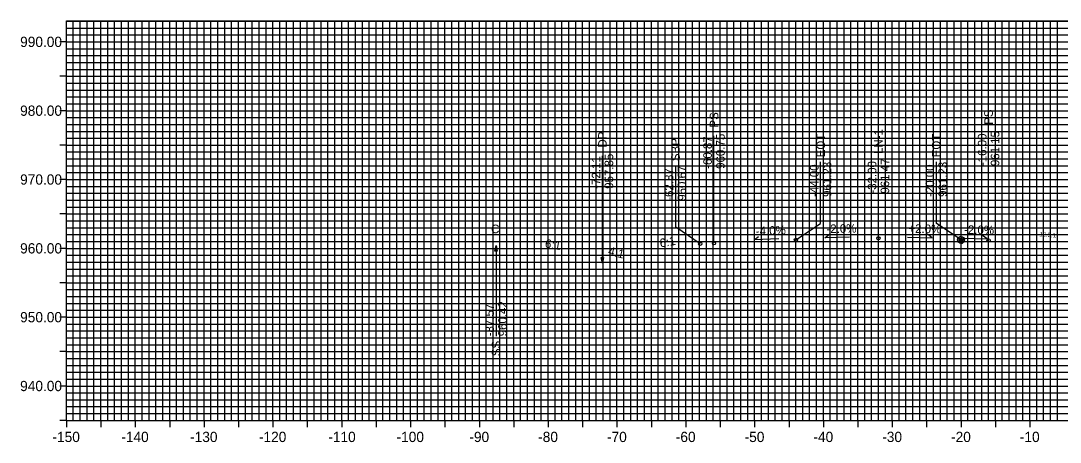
# Model space of a CAD drawing. Extents: x -157 to 156, y 932 to 993.
# Drawn here: x -156.6 to -5.6, y 931.8 to 993.1 of the extents above; entities that cross this region are included whole.
import ezdxf

# ---------------------------------------------------------------- set-up
doc = ezdxf.new("R2010")
doc.units = 0
for name, color, linetype in [('E_NCDOT_Terrain_Model_Boundary', 7, 'Continuous'), ('E_NCDOT_Terrain_Model_Breakline', 7, 'Continuous'), ('E_NCDOT_Terrain_Model_Contour_Minor', 7, 'Continuous'), ('E_NCDOT_Terrain_Model_Flow_Arrows', 7, 'Continuous'), ('E_NCDOT_Terrain_Model_Hole', 7, 'Continuous'), ('E_NCDOT_Terrain_Model_Island', 7, 'Continuous'), ('E_NCDOT_Terrain_Model_Points_High', 7, 'Continuous'), ('E_NCDOT_Terrain_Model_Points_Low', 7, 'Continuous'), ('E_NCDOT_Terrain_Model_Triangles', 7, 'Continuous'), ('E_NCDOT_Vertical_Profile_Ground_Line', 7, 'Continuous'), ('P_HYD_Contour_Major', 7, 'Continuous'), ('P_HYD_Contour_Minor', 7, 'Continuous'), ('P_HYD_TL_Ditch_Boundary', 7, 'Continuous')]:
    doc.layers.add(name, color=color, linetype=linetype)

msp = doc.modelspace()

# ---------------------------------------------------------------- linework, layer by layer
at = {"layer": 'E_NCDOT_Terrain_Model_Boundary'}
for p, q in [((-50.07, 961.23), (-49.41, 961.73)), ((-46.48, 961.37), (-50.07, 961.23)), ((-39.8, 961.55), (-39.12, 962.05)), ((-36.2, 961.62), (-39.8, 961.55)), ((-27.8, 961.62), (-24.2, 961.55)), ((-24.2, 961.55), (-24.88, 962.05)), ((-19.8, 961.46), (-16.2, 961.39)), ((-16.2, 961.39), (-16.88, 961.89))]:
    msp.add_line(p, q, dxfattribs=at)
at = {"layer": 'E_NCDOT_Terrain_Model_Breakline'}
for p, q in [((-140, 935), (-140, 993.06)), ((-130, 935), (-130, 993.06)), ((-120, 935), (-120, 993.06)), ((-110, 935), (-110, 993.06)), ((-100, 935), (-100, 993.06)), ((-90, 935), (-90, 993.06)), ((-80, 935), (-80, 993.06)), ((-70, 935), (-70, 993.06)), ((-60, 935), (-60, 993.06)), ((-50, 935), (-50, 993.06)), ((-40, 935), (-40, 993.06)), ((-30, 935), (-30, 993.06)), ((-20, 935), (-20, 993.06)), ((-10, 935), (-10, 993.06)), ((-150, 990), (150, 990)), ((-150, 980), (150, 980)), ((-150, 970), (150, 970)), ((-150, 960), (150, 960)), ((-150, 950), (150, 950)), ((-150, 940), (150, 940))]:
    msp.add_line(p, q, dxfattribs=at)
at = {"layer": 'E_NCDOT_Terrain_Model_Flow_Arrows'}
for p, q in [((-150, 993.06), (150, 993.06)), ((-150, 935), (-150, 993.06)), ((-150, 935), (150, 935))]:
    msp.add_line(p, q, dxfattribs=at)
at = {"layer": 'E_NCDOT_Terrain_Model_Island'}
for p, q in [((-20.5, 961.23), (-19.5, 961.23)), ((-20.5, 961.23), (-19.5, 961.23)), ((-20, 961.73), (-20, 960.73)), ((-20, 961.73), (-20, 960.73))]:
    msp.add_line(p, q, dxfattribs=at)
for points in [[(-20.5, 961.23), (-20, 961.23), (-20, 961.73)], [(-20.5, 961.23), (-20, 961.23), (-20, 961.73)], [(-19.5, 961.23), (-20, 961.23), (-20, 960.73)], [(-19.5, 961.23), (-20, 961.23), (-20, 960.73)]]:
    msp.add_lwpolyline(points, dxfattribs=at)
msp.add_circle((-20, 961.23), 0.5, dxfattribs=at)
msp.add_circle((-20, 961.23), 0.5, dxfattribs=at)
for start, end in [(90, 180), (90, 180), (270, 0), (270, 0)]:
    msp.add_arc((-20, 961.23), 0.5, start, end, dxfattribs=at)
at = {"layer": 'E_NCDOT_Terrain_Model_Points_High'}
for p, q in [((-150, 993), (150, 993)), ((-149, 935), (-149, 993.06)), ((-148, 935), (-148, 993.06)), ((-147, 935), (-147, 993.06)), ((-146, 935), (-146, 993.06)), ((-144, 935), (-144, 993.06)), ((-143, 935), (-143, 993.06)), ((-142, 935), (-142, 993.06)), ((-141, 935), (-141, 993.06)), ((-139, 935), (-139, 993.06)), ((-138, 935), (-138, 993.06)), ((-137, 935), (-137, 993.06)), ((-136, 935), (-136, 993.06)), ((-134, 935), (-134, 993.06)), ((-133, 935), (-133, 993.06)), ((-132, 935), (-132, 993.06)), ((-131, 935), (-131, 993.06)), ((-129, 935), (-129, 993.06)), ((-128, 935), (-128, 993.06)), ((-127, 935), (-127, 993.06)), ((-126, 935), (-126, 993.06)), ((-124, 935), (-124, 993.06)), ((-123, 935), (-123, 993.06)), ((-122, 935), (-122, 993.06)), ((-121, 935), (-121, 993.06)), ((-119, 935), (-119, 993.06)), ((-118, 935), (-118, 993.06)), ((-117, 935), (-117, 993.06)), ((-116, 935), (-116, 993.06)), ((-114, 935), (-114, 993.06)), ((-113, 935), (-113, 993.06)), ((-112, 935), (-112, 993.06)), ((-111, 935), (-111, 993.06)), ((-109, 935), (-109, 993.06)), ((-108, 935), (-108, 993.06)), ((-107, 935), (-107, 993.06)), ((-106, 935), (-106, 993.06)), ((-104, 935), (-104, 993.06)), ((-103, 935), (-103, 993.06)), ((-102, 935), (-102, 993.06)), ((-101, 935), (-101, 993.06)), ((-99, 935), (-99, 993.06)), ((-98, 935), (-98, 993.06)), ((-97, 935), (-97, 993.06)), ((-96, 935), (-96, 993.06)), ((-94, 935), (-94, 993.06)), ((-93, 935), (-93, 993.06)), ((-92, 935), (-92, 993.06)), ((-91, 935), (-91, 993.06)), ((-89, 935), (-89, 993.06)), ((-88, 935), (-88, 993.06)), ((-87, 935), (-87, 993.06)), ((-86, 935), (-86, 993.06)), ((-84, 935), (-84, 993.06)), ((-83, 935), (-83, 993.06)), ((-82, 935), (-82, 993.06)), ((-81, 935), (-81, 993.06)), ((-79, 935), (-79, 993.06)), ((-78, 935), (-78, 993.06)), ((-77, 935), (-77, 993.06)), ((-76, 935), (-76, 993.06)), ((-74, 935), (-74, 993.06)), ((-73, 935), (-73, 993.06)), ((-72, 935), (-72, 993.06)), ((-71, 935), (-71, 993.06)), ((-69, 935), (-69, 993.06)), ((-68, 935), (-68, 993.06)), ((-67, 935), (-67, 993.06)), ((-66, 935), (-66, 993.06)), ((-64, 935), (-64, 993.06)), ((-63, 935), (-63, 993.06)), ((-62, 935), (-62, 993.06)), ((-61, 935), (-61, 993.06)), ((-59, 935), (-59, 993.06)), ((-58, 935), (-58, 993.06)), ((-57, 935), (-57, 993.06)), ((-56, 935), (-56, 993.06)), ((-54, 935), (-54, 993.06)), ((-53, 935), (-53, 993.06)), ((-52, 935), (-52, 993.06)), ((-51, 935), (-51, 993.06)), ((-49, 935), (-49, 993.06)), ((-48, 935), (-48, 993.06)), ((-47, 935), (-47, 993.06)), ((-46, 935), (-46, 993.06)), ((-44, 935), (-44, 993.06)), ((-43, 935), (-43, 993.06)), ((-42, 935), (-42, 993.06)), ((-41, 935), (-41, 993.06)), ((-39, 935), (-39, 993.06)), ((-38, 935), (-38, 993.06)), ((-37, 935), (-37, 993.06)), ((-36, 935), (-36, 993.06)), ((-34, 935), (-34, 993.06)), ((-33, 935), (-33, 993.06)), ((-32, 935), (-32, 993.06)), ((-31, 935), (-31, 993.06)), ((-29, 935), (-29, 993.06)), ((-28, 935), (-28, 993.06)), ((-27, 935), (-27, 993.06)), ((-26, 935), (-26, 993.06)), ((-24, 935), (-24, 993.06)), ((-23, 935), (-23, 993.06)), ((-22, 935), (-22, 993.06)), ((-21, 935), (-21, 993.06)), ((-19, 935), (-19, 993.06)), ((-18, 935), (-18, 993.06)), ((-17, 935), (-17, 993.06)), ((-16, 935), (-16, 993.06)), ((-14, 935), (-14, 993.06)), ((-13, 935), (-13, 993.06)), ((-12, 935), (-12, 993.06)), ((-11, 935), (-11, 993.06)), ((-9, 935), (-9, 993.06)), ((-8, 935), (-8, 993.06)), ((-7, 935), (-7, 993.06)), ((-6, 935), (-6, 993.06)), ((-150, 992), (150, 992)), ((-150, 991), (150, 991)), ((-150, 989), (150, 989)), ((-150, 988), (150, 988)), ((-150, 987), (150, 987)), ((-150, 986), (150, 986)), ((-150, 984), (150, 984)), ((-150, 983), (150, 983)), ((-150, 982), (150, 982)), ((-150, 981), (150, 981)), ((-150, 979), (150, 979)), ((-150, 978), (150, 978)), ((-150, 977), (150, 977)), ((-150, 976), (150, 976)), ((-150, 974), (150, 974)), ((-150, 973), (150, 973)), ((-150, 972), (150, 972)), ((-150, 971), (150, 971)), ((-150, 969), (150, 969)), ((-150, 968), (150, 968)), ((-150, 967), (150, 967)), ((-150, 966), (150, 966)), ((-150, 964), (150, 964)), ((-150, 963), (150, 963)), ((-150, 962), (150, 962)), ((-150, 961), (150, 961)), ((-150, 959), (150, 959)), ((-150, 958), (150, 958)), ((-150, 957), (150, 957)), ((-150, 956), (150, 956)), ((-150, 954), (150, 954)), ((-150, 953), (150, 953)), ((-150, 952), (150, 952)), ((-150, 951), (150, 951)), ((-150, 949), (150, 949)), ((-150, 948), (150, 948)), ((-150, 947), (150, 947)), ((-150, 946), (150, 946)), ((-150, 944), (150, 944)), ((-150, 943), (150, 943)), ((-150, 942), (150, 942)), ((-150, 941), (150, 941)), ((-150, 939), (150, 939)), ((-150, 938), (150, 938)), ((-150, 937), (150, 937)), ((-150, 936), (150, 936))]:
    msp.add_line(p, q, dxfattribs=at)
at = {"layer": 'E_NCDOT_Terrain_Model_Points_Low'}
for p, q in [((-145, 935), (-145, 993.06)), ((-140, 935), (-140, 993.06)), ((-135, 935), (-135, 993.06)), ((-130, 935), (-130, 993.06)), ((-125, 935), (-125, 993.06)), ((-120, 935), (-120, 993.06)), ((-115, 935), (-115, 993.06)), ((-110, 935), (-110, 993.06)), ((-105, 935), (-105, 993.06)), ((-100, 935), (-100, 993.06)), ((-95, 935), (-95, 993.06)), ((-90, 935), (-90, 993.06)), ((-85, 935), (-85, 993.06)), ((-80, 935), (-80, 993.06)), ((-75, 935), (-75, 993.06)), ((-70, 935), (-70, 993.06)), ((-65, 935), (-65, 993.06)), ((-60, 935), (-60, 993.06)), ((-55, 935), (-55, 993.06)), ((-50, 935), (-50, 993.06)), ((-45, 935), (-45, 993.06)), ((-40, 935), (-40, 993.06)), ((-35, 935), (-35, 993.06)), ((-30, 935), (-30, 993.06)), ((-25, 935), (-25, 993.06)), ((-20, 935), (-20, 993.06)), ((-15, 935), (-15, 993.06)), ((-10, 935), (-10, 993.06)), ((-150, 990), (-150.96, 990)), ((-150, 990), (150, 990)), ((-150, 985), (-150.96, 985)), ((-150, 985), (150, 985)), ((-150, 980), (-150.96, 980)), ((-150, 980), (150, 980)), ((-150, 975), (-150.96, 975)), ((-150, 975), (150, 975)), ((-150, 970), (-150.96, 970)), ((-150, 970), (150, 970)), ((-150, 965), (-150.96, 965)), ((-150, 965), (150, 965)), ((-150, 960), (-150.96, 960)), ((-150, 960), (150, 960)), ((-150, 955), (-150.96, 955)), ((-150, 955), (150, 955)), ((-150, 950), (-150.96, 950)), ((-150, 950), (150, 950)), ((-150, 945), (-150.96, 945)), ((-150, 945), (150, 945)), ((-150, 940), (-150.96, 940)), ((-150, 940), (150, 940)), ((-150, 935), (-150.96, 935)), ((-150, 935), (-150, 934.04)), ((-145, 935), (-145, 934.04)), ((-140, 935), (-140, 934.04)), ((-135, 935), (-135, 934.04)), ((-130, 935), (-130, 934.04)), ((-125, 935), (-125, 934.04)), ((-120, 935), (-120, 934.04)), ((-115, 935), (-115, 934.04)), ((-110, 935), (-110, 934.04)), ((-105, 935), (-105, 934.04)), ((-100, 935), (-100, 934.04)), ((-95, 935), (-95, 934.04)), ((-90, 935), (-90, 934.04)), ((-85, 935), (-85, 934.04)), ((-80, 935), (-80, 934.04)), ((-75, 935), (-75, 934.04)), ((-70, 935), (-70, 934.04)), ((-65, 935), (-65, 934.04)), ((-60, 935), (-60, 934.04)), ((-55, 935), (-55, 934.04)), ((-50, 935), (-50, 934.04)), ((-45, 935), (-45, 934.04)), ((-40, 935), (-40, 934.04)), ((-35, 935), (-35, 934.04)), ((-30, 935), (-30, 934.04)), ((-25, 935), (-25, 934.04)), ((-20, 935), (-20, 934.04)), ((-15, 935), (-15, 934.04)), ((-10, 935), (-10, 934.04))]:
    msp.add_line(p, q, dxfattribs=at)
at = {"layer": 'E_NCDOT_Terrain_Model_Triangles'}
for p, q in [((-61.46, 963.07), (-61.46, 972.02)), ((-40.44, 963.62), (-40.44, 972.58)), ((-23.56, 963.62), (-23.56, 972.58)), ((-57.9, 960.67), (-61.46, 963.07)), ((-44, 961.23), (-40.44, 963.62)), ((-20, 961.23), (-23.56, 963.62))]:
    msp.add_line(p, q, dxfattribs=at)
at = {"layer": 'E_NCDOT_Vertical_Profile_Ground_Line'}
for p, q in [((-55.9, 960.75), (-55.9, 976.35)), ((-16, 961.15), (-16, 976.75)), ((-72.11, 957.85), (-72.11, 973.45)), ((-32, 961.47), (-32, 973.59)), ((-87.57, 960.42), (-87.57, 947.22))]:
    msp.add_line(p, q, dxfattribs=at)
for points in [[(-87.57, 960.42), (-87.39, 959.6), (-87.74, 959.6)], [(-72.11, 957.85), (-72.29, 958.67), (-71.94, 958.67)]]:
    msp.add_lwpolyline(points, close=True, dxfattribs=at)
for centre in [(-57.9, 960.67), (-55.9, 960.75), (-44, 961.23), (-32, 961.47), (-20, 961.23), (-16, 961.15)]:
    msp.add_circle(centre, 0.24, dxfattribs=at)

# ---------------------------------------------------------------- texts
at = {"layer": 'E_NCDOT_Terrain_Model_Contour_Minor'}
for s, p in [('DP', (-71.49, 974.65)), ('-72.11', (-72.42, 968.65)), ('957.85', (-70.55, 968.65)), ('-87.57', (-87.88, 947.22)), ('960.42', (-86.01, 947.22)), ('SS', (-86.94, 944.34))]:
    msp.add_text(s, height=1.248, rotation=90, dxfattribs=at).set_placement(p)
msp.add_text('C', height=1.25, dxfattribs=at).set_placement((-88.29, 962.2))
at = {"layer": 'E_NCDOT_Terrain_Model_Hole'}
for s, p in [('990.00', (-156.73, 989.26)), ('980.00', (-156.73, 979.26)), ('970.00', (-156.73, 969.26)), ('960.00', (-156.73, 959.26)), ('950.00', (-156.73, 949.26)), ('940.00', (-156.73, 939.26)), ('-150', (-152.03, 931.86)), ('-140', (-142.03, 931.86)), ('-130', (-132.03, 931.86)), ('-120', (-122.03, 931.86)), ('-110', (-111.95, 931.86)), ('-100', (-102.03, 931.86)), ('-90', (-91.45, 931.86)), ('-80', (-81.45, 931.86)), ('-70', (-71.45, 931.86)), ('-60', (-61.45, 931.86)), ('-50', (-51.45, 931.86)), ('-40', (-41.45, 931.86)), ('-30', (-31.45, 931.86)), ('-20', (-21.45, 931.86)), ('-10', (-11.45, 931.86))]:
    msp.add_text(s, height=1.488, dxfattribs=at).set_placement(p)
at = {"layer": 'P_HYD_Contour_Major'}
for s, rotation, p in [('-2.0%', 1.1458, (-39.55, 962.21)), ('+2.0%', 358.8542, (-27.66, 962.27))]:
    msp.add_text(s, height=1.248, rotation=rotation, dxfattribs=at).set_placement(p)
at = {"layer": 'P_HYD_Contour_Minor'}
for s, height, rotation, p in [('-4.0%', 1.248, 2.2906, (-49.8, 961.88)), ('-2.0%', 1.248, 358.8542, (-19.57, 962.11)), ('12.5:1', 0.624, 355.4261, (-8.62, 961.76)), ('6:1', 1.248, 350.5358, (-80.53, 960.13)), ('6:1', 1.248, 9.4639, (-63.69, 960.13)), ('4:1', 1.248, 345.9638, (-71.37, 959.07))]:
    msp.add_text(s, height=height, rotation=rotation, dxfattribs=at).set_placement(p)
at = {"layer": 'P_HYD_TL_Ditch_Boundary'}
for s, p in [('PS', (-55.27, 977.55)), ('PS', (-15.38, 977.95)), ('SBP', (-60.87, 972.67)), ('-60.87', (-56.21, 971.55)), ('960.75', (-54.34, 971.55)), ('EOT', (-39.78, 973.23)), ('LN-1', (-31.38, 973.71)), ('EOT', (-22.98, 973.23)), ('-16.00', (-16.31, 971.95)), ('961.15', (-14.44, 971.95)), ('961.47', (-30.44, 967.95)), ('-62.87', (-61.81, 966.91)), ('960.67', (-59.94, 966.91)), ('-44.00', (-40.71, 967.47)), ('961.23', (-38.84, 967.47)), ('-32.00', (-32.31, 967.95)), ('-20.00', (-23.91, 967.47)), ('961.23', (-22.04, 967.47))]:
    msp.add_text(s, height=1.248, rotation=90, dxfattribs=at).set_placement(p)

doc.saveas('drawing.dxf')
